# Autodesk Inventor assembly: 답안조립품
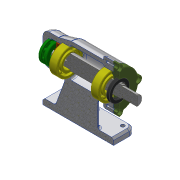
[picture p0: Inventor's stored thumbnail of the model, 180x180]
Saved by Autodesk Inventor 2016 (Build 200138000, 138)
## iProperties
Created: 2019-07
Part Number: 답안조립품
Material: 일반
Document SubType Name: Assembly
Designer: 605-12
Author: 605-12
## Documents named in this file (9)
- C:\Users\605-12\Desktop\490704V1074\답안조립품.iam
- C:\Users\605-12\Desktop\490704V1074\490704V1074.ipt
- C:\Users\605-12\Desktop\490704V1074\베어링 6004.ipt
- C:\Users\605-12\Desktop\490704V1074\축.ipt
- C:\Users\605-12\Desktop\490704V1074\베어링 51202.ipt
- C:\Users\605-12\Desktop\490704V1074\어댑터슬리브.ipt
- C:\Users\605-12\Desktop\490704V1074\볼트 M4.ipt
- C:\Users\605-12\Desktop\490704V1074\커버.ipt
- C:\Users\605-12\Desktop\490704V1074\오일 실.ipt
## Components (1 placed, 1 different names)
1. 490704V1074:1
